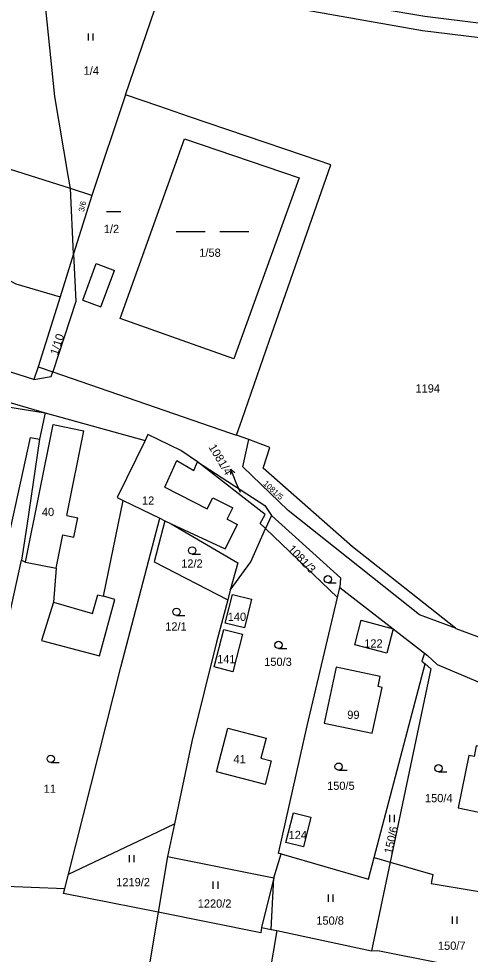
# Model space of a CAD drawing. Extents: x -746176 to -739709, y -1128407 to -1124482.
# Drawn here: x -742101.3 to -742008.2, y -1126433.2 to -1126240.2 of the extents above; entities that cross this region are included whole.
import ezdxf

# ---------------------------------------------------------------- set-up
doc = ezdxf.new("R2010")
doc.units = 0
for name, color, linetype in [('Hranice parcel', 7, 'Continuous'), ('Parcelní čísla', 7, 'Continuous'), ('Pop  PČ popisy', 7, 'Continuous'), ('Vnitřní kresba', 7, 'Continuous'), ('Značky kultur', 7, 'Continuous')]:
    doc.layers.add(name, color=color, linetype=linetype)

msp = doc.modelspace()

# ---------------------------------------------------------------- linework, layer by layer
at = {"layer": 'Hranice parcel'}
for p, q in [((-742079.26, -1126255.9), (-742071.8, -1126233.98)), ((-742079.26, -1126255.9), (-742086.23, -1126276.66)), ((-742090.65, -1126275.25), (-742116.22, -1126267.19)), ((-742090.65, -1126275.25), (-742091.11, -1126272.55)), ((-742089.98, -1126288.73), (-742090.65, -1126275.25)), ((-742086.23, -1126276.66), (-742090.65, -1126275.25)), ((-742086.23, -1126276.66), (-742089.98, -1126288.73)), ((-742089.98, -1126288.73), (-742092.74, -1126297.6)), ((-742120.66, -1126314.22), (-742095.86, -1126321.55)), ((-742106.07, -1126319.87), (-742095.86, -1126321.55)), ((-742095.86, -1126321.55), (-742097.02, -1126326.92)), ((-742095.86, -1126321.55), (-742075.26, -1126327.22)), ((-742053.88, -1126327.04), (-742056.42, -1126326.16)), ((-742079.74, -1126339.61), (-742072.2, -1126343.28)), ((-742072.2, -1126343.28), (-742071.19, -1126343.77)), ((-742049.16, -1126342.68), (-742050.39, -1126345.41)), ((-742035.57, -1126359.6), (-742050.39, -1126345.41)), ((-742105.28, -1126372.36), (-742100.72, -1126351.93)), ((-742056.12, -1126352.45), (-742057.69, -1126358.14)), ((-742057.69, -1126358.14), (-742058.21, -1126360.09)), ((-742035.57, -1126359.6), (-742035.1, -1126357.57)), ((-742058.21, -1126360.09), (-742060.53, -1126368.87)), ((-742028.01, -1126413.28), (-742017.48, -1126373.34)), ((-742069.18, -1126406.33), (-742070.6, -1126413.05)), ((-742070.6, -1126413.05), (-742072.53, -1126424.54)), ((-742070.6, -1126413.05), (-742048.68, -1126417.48)), ((-742048.68, -1126417.48), (-742047.21, -1126412.52)), ((-742024.68, -1126414.24), (-742028.56, -1126432.53)), ((-742028.01, -1126413.28), (-742024.68, -1126414.24)), ((-742091.83, -1126419.68), (-742091.05, -1126416.72)), ((-742113.18, -1126418.78), (-742091.83, -1126419.68)), ((-742048.68, -1126417.48), (-742051.23, -1126427.71)), ((-742072.53, -1126424.54), (-742085.13, -1126499.75)), ((-742048.06, -1126428.34), (-742062.27, -1126510.43)), ((-742048.06, -1126428.34), (-742028.56, -1126432.53))]:
    msp.add_line(p, q, dxfattribs=at)
for points in [[(-742091.11, -1126272.55), (-742093.87, -1126256.26), (-742095.72, -1126238.15), (-742097.01, -1126230.58)], [(-741979.16, -1126247.44), (-742018.02, -1126242.67), (-742051.56, -1126236.78), (-742071.8, -1126233.98)], [(-742037.23, -1126236.37), (-742017.58, -1126239.71), (-741978.86, -1126244.46), (-741935.37, -1126247.86), (-741906.75, -1126240.11), (-741905.97, -1126243.01), (-741935.09, -1126250.9), (-741979.16, -1126247.44)], [(-742056.42, -1126326.16), (-742055.26, -1126322.85), (-742049.63, -1126306.73), (-742036.93, -1126270.38), (-742042.58, -1126268.45), (-742066.08, -1126260.42), (-742072.41, -1126258.25), (-742079.26, -1126255.9)], [(-742080.37, -1126302.09), (-742067.12, -1126265.01), (-742043.47, -1126273.03), (-742056.95, -1126310.39), (-742080.37, -1126302.09)], [(-742119.31, -1126276.84), (-742118.96, -1126285.81), (-742101.9, -1126294.87), (-742092.74, -1126297.6)], [(-742089.98, -1126288.73), (-742089.5, -1126298.57), (-742094.3, -1126313.08)], [(-742098.16, -1126314.66), (-742107.1, -1126311.81), (-742124.49, -1126306.28), (-742152.92, -1126294.67), (-742154.48, -1126293.27)], [(-742092.74, -1126297.6), (-742097.33, -1126312.04), (-742098.16, -1126314.66)], [(-742098.16, -1126314.66), (-742094.61, -1126314.04), (-742094.3, -1126313.08)], [(-742094.3, -1126313.08), (-742057.82, -1126325.67), (-742056.42, -1126326.16)], [(-742064.45, -1126331.63), (-742067.87, -1126329.27), (-742074.66, -1126325.97), (-742075.26, -1126327.22)], [(-742108.8, -1126371.54), (-742098.88, -1126326.64), (-742097.02, -1126326.92)], [(-742097.02, -1126326.92), (-742099.61, -1126344.81), (-742100.72, -1126351.93)], [(-742075.26, -1126327.22), (-742081, -1126339.01), (-742079.74, -1126339.61)], [(-742011.25, -1126365.95), (-742018.63, -1126363.2), (-742045.74, -1126341.65), (-742055.06, -1126332.67), (-742053.88, -1126327.04)], [(-742011.25, -1126365.95), (-742032.44, -1126349.16), (-742050.91, -1126332.94), (-742049.54, -1126328.65), (-742053.88, -1126327.04)], [(-742050.39, -1126345.41), (-742051.51, -1126344.33), (-742050.48, -1126342.5), (-742064.45, -1126331.63)], [(-742064.45, -1126331.63), (-742050.58, -1126340.65), (-742049.16, -1126342.68)], [(-742100.72, -1126351.93), (-742099.9, -1126352.31), (-742093.57, -1126353.58), (-742094.13, -1126360.58), (-742096.61, -1126368.48), (-742084.66, -1126371.69), (-742081.5, -1126360.05), (-742083.81, -1126359.38), (-742079.74, -1126339.61)], [(-742091.05, -1126416.72), (-742080.28, -1126374.02), (-742072.2, -1126343.28)], [(-742049.16, -1126342.68), (-742034.95, -1126355.55), (-742035.1, -1126357.57)], [(-742071.19, -1126343.77), (-742073.35, -1126352.28), (-742058.21, -1126360.09)], [(-742071.19, -1126343.77), (-742069.89, -1126344.4), (-742056.12, -1126352.45)], [(-742057.69, -1126358.14), (-742053.45, -1126352.23), (-742050.39, -1126345.41)], [(-742054.77, -1126365.88), (-742058.74, -1126364.92), (-742057.24, -1126358.99), (-742053.27, -1126359.99), (-742054.77, -1126365.88)], [(-742035.1, -1126357.57), (-742024.1, -1126366.11), (-742017.65, -1126371.11)], [(-742047.21, -1126412.52), (-742047.73, -1126412.44), (-742041.81, -1126386.09), (-742035.57, -1126359.6)], [(-742024.1, -1126366.11), (-742025.41, -1126371.14), (-742032, -1126369.36), (-742030.67, -1126364.32), (-742024.1, -1126366.11)], [(-742058.98, -1126366.22), (-742055.17, -1126367.22), (-742057.16, -1126374.93), (-742061.01, -1126373.94), (-742058.98, -1126366.22)], [(-741995.94, -1126371.66), (-741996.93, -1126371.29), (-742011.08, -1126366.08), (-742011.25, -1126365.95)], [(-742060.53, -1126368.87), (-742065.58, -1126389.34), (-742069.18, -1126406.33)], [(-742017.65, -1126371.11), (-742018.15, -1126372.75), (-742017.48, -1126373.34)], [(-742017.65, -1126371.11), (-742017.02, -1126371.6), (-742014.99, -1126373.44), (-741986.71, -1126385.43)], [(-742026.38, -1126378.16), (-742027.21, -1126377.99), (-742026.77, -1126375.94), (-742035.82, -1126374), (-742038.29, -1126385.53), (-742028.41, -1126387.64), (-742026.38, -1126378.16)], [(-742017.48, -1126373.34), (-742016.3, -1126374.36), (-742024.68, -1126414.24)], [(-742051.38, -1126392.8), (-742049.23, -1126393.33), (-742050.47, -1126398.22), (-742060.55, -1126395.61), (-742058.21, -1126386.6), (-742050.31, -1126388.63), (-742051.38, -1126392.8)], [(-742003.87, -1126389.15), (-742004.21, -1126390.8), (-742006.94, -1126390.24), (-742007.38, -1126392.41), (-742008.47, -1126392.19), (-742010.7, -1126403.03), (-742000.83, -1126405.05), (-741997.82, -1126390.4), (-742003.87, -1126389.15)], [(-742044.65, -1126404.04), (-742041.06, -1126404.95), (-742042.6, -1126411.06), (-742046.19, -1126410.15), (-742044.65, -1126404.04)], [(-742091.05, -1126416.72), (-742074.03, -1126408.64), (-742069.18, -1126406.33)], [(-742047.21, -1126412.52), (-742029.18, -1126417.71), (-742028.01, -1126413.28)], [(-742024.68, -1126414.24), (-742015.91, -1126416.77), (-742016.26, -1126418.65), (-742006.36, -1126420.29)], [(-742072.53, -1126424.54), (-742092.04, -1126420.67), (-742091.83, -1126419.68)], [(-742051.23, -1126427.71), (-742051.35, -1126428.82), (-742072.53, -1126424.54)], [(-742051.23, -1126427.71), (-742049.27, -1126428.1), (-742048.06, -1126428.34)], [(-742028.56, -1126432.53), (-742027.22, -1126432.46), (-742014.43, -1126435)]]:
    msp.add_lwpolyline(points, dxfattribs=at)
at = {"layer": 'Pop  PČ popisy'}
for p, q in [((-742057.55, -1126333.16), (-742057.64, -1126334.27)), ((-742056.43, -1126335.94), (-742057.55, -1126333.16)), ((-742057.55, -1126333.16), (-742056.71, -1126333.9)), ((-742055.59, -1126337.98), (-742056.43, -1126335.94))]:
    msp.add_line(p, q, dxfattribs=at)
at = {"layer": 'Vnitřní kresba'}
for p, q in [((-742088.12, -1126298.3), (-742085.35, -1126290.74)), ((-742085.35, -1126290.74), (-742081.58, -1126292.13)), ((-742084.35, -1126299.68), (-742081.58, -1126292.13)), ((-742088.12, -1126298.3), (-742084.35, -1126299.68)), ((-742097.33, -1126312.04), (-742094.3, -1126313.08)), ((-742099.9, -1126352.31), (-742094.21, -1126323.93)), ((-742094.21, -1126323.93), (-742087.88, -1126325.2)), ((-742091.39, -1126342.7), (-742087.88, -1126325.2)), ((-742071.15, -1126336.85), (-742068.73, -1126331.35)), ((-742068.73, -1126331.35), (-742065.22, -1126333.43)), ((-742065.22, -1126333.43), (-742064.45, -1126331.63)), ((-742071.15, -1126336.85), (-742062.44, -1126341.34)), ((-742062.44, -1126341.34), (-742061.28, -1126339.07)), ((-742061.28, -1126339.07), (-742057.13, -1126341.13)), ((-742058.33, -1126343.46), (-742057.13, -1126341.13)), ((-742091.39, -1126342.7), (-742089.14, -1126343.15)), ((-742089.94, -1126347.14), (-742089.14, -1126343.15)), ((-742058.33, -1126343.46), (-742056.16, -1126344.57)), ((-742069.89, -1126344.4), (-742058.75, -1126349.59)), ((-742058.75, -1126349.59), (-742056.16, -1126344.57)), ((-742093.57, -1126353.58), (-742092.19, -1126346.69)), ((-742092.19, -1126346.69), (-742089.94, -1126347.14)), ((-742086.12, -1126362.9), (-742085, -1126359.04)), ((-742085, -1126359.04), (-742083.81, -1126359.38)), ((-742094.13, -1126360.58), (-742086.12, -1126362.9)), ((-742049.27, -1126428.1), (-742048.68, -1126417.48))]:
    msp.add_line(p, q, dxfattribs=at)
at = {"layer": 'Značky kultur'}
for p, q in [((-742086.94, -1126244.72), (-742086.94, -1126243.22)), ((-742085.94, -1126244.72), (-742085.94, -1126243.22)), ((-742083.24, -1126280.01), (-742080.24, -1126280.01)), ((-742068.85, -1126284.1), (-742062.85, -1126284.1)), ((-742059.85, -1126284.1), (-742053.85, -1126284.1)), ((-742065.54, -1126350.67), (-742063.79, -1126350.67)), ((-742037.57, -1126356.61), (-742035.82, -1126356.61)), ((-742068.77, -1126363.34), (-742067.02, -1126363.34)), ((-742047.73, -1126370.16), (-742045.98, -1126370.16)), ((-742094.71, -1126393.67), (-742092.96, -1126393.67)), ((-742035.33, -1126395.27), (-742033.58, -1126395.27)), ((-742014.74, -1126395.61), (-742012.99, -1126395.61)), ((-742024.8, -1126405.99), (-742024.8, -1126404.49)), ((-742023.8, -1126405.99), (-742023.8, -1126404.49)), ((-742078.48, -1126414.25), (-742078.48, -1126412.75)), ((-742077.48, -1126414.25), (-742077.48, -1126412.75)), ((-742061.18, -1126419.71), (-742061.18, -1126418.21)), ((-742060.18, -1126419.71), (-742060.18, -1126418.21)), ((-742037.45, -1126422.4), (-742037.45, -1126420.9)), ((-742036.45, -1126422.4), (-742036.45, -1126420.9)), ((-742011.86, -1126426.93), (-742011.86, -1126425.43)), ((-742010.86, -1126426.93), (-742010.86, -1126425.43))]:
    msp.add_line(p, q, dxfattribs=at)
for centre in [(-742065.54, -1126349.92), (-742037.57, -1126355.86), (-742068.77, -1126362.59), (-742047.73, -1126369.41), (-742094.71, -1126392.92), (-742035.33, -1126394.52), (-742014.74, -1126394.86)]:
    msp.add_circle(centre, 0.75, dxfattribs=at)

# ---------------------------------------------------------------- texts
at = {"layer": 'Parcelní čísla'}
for s, p in [('1/4', (-742087.92, -1126251.76)), ('1/2', (-742083.77, -1126284.43)), ('1/58', (-742064.07, -1126289.33)), ('1194', (-742019.48, -1126317.33)), ('12', (-742075.89, -1126340.47)), ('40', (-742096.53, -1126342.82)), ('12/2', (-742067.79, -1126353.46)), ('140', (-742058.2, -1126364.45)), ('12/1', (-742071.09, -1126366.45)), ('122', (-742030.05, -1126369.95)), ('141', (-742060.39, -1126373.18)), ('150/3', (-742050.68, -1126373.74)), ('99', (-742033.55, -1126384.67)), ('41', (-742057.02, -1126393.81)), ('150/5', (-742037.71, -1126399.31)), ('11', (-742096.16, -1126399.92)), ('150/4', (-742017.52, -1126401.86)), ('124', (-742045.65, -1126409.47)), ('1219/2', (-742081.2, -1126419.2)), ('1220/2', (-742064.39, -1126423.62)), ('150/8', (-742039.93, -1126427.13)), ('150/7', (-742014.85, -1126432.31))]:
    msp.add_text(s, height=1.7, dxfattribs=at).set_placement(p)
for s, height, rotation, p in [('3/6', 1.19, 76, (-742087.87, -1126280.14)), ('1/10', 1.7, 72, (-742093.27, -1126309.76)), ('1081/4', 1.7, 301, (-742062.21, -1126328.6)), ('1081/5', 1.19, 317, (-742050.97, -1126336.27)), ('1081/3', 1.7, 314, (-742045.93, -1126349.76)), ('150/6', 1.7, 77, (-742024.33, -1126412.62))]:
    msp.add_text(s, height=height, rotation=rotation, dxfattribs=at).set_placement(p)

doc.saveas('drawing.dxf')
